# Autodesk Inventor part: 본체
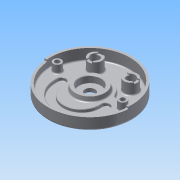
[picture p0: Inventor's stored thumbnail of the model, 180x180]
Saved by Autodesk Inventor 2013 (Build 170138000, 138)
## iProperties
Created: 2015-04
Part Number: 본체
Material: 알루미늄 6061
Document SubType Name: Modeling
Designer: Administrator
Density: 2.71 g/cm^3
Mass: 1042.47 g
Surface Area: 1020.69 cm^2
Volume: 384.675 cm^3
Author: Administrator
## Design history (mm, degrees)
sketch "스케치1"
  geometry: C1 r 95 at (0, 0); 1 further point
  constraints: 1 centre point, 1 coincident
  dimensions: "d0" = 95 radius of C1
extrude "돌출1" new body sketch "스케치1" distance "d1" = 27; taper "d2" = 0 deg
feature "쉘1" dims "d3" = 7, "d4" = 5
sketch "스케치2"
  geometry: L1 (-94.638, -8.28)-(-89.658, -7.844); L2 (89.658, -7.844)-(94.638, -8.28); L3 (0, 0)-(85.276, 0); L4 (-89.658, -7.844)-(0, 0); L5 (0, 0)-(89.658, -7.844); C1 r 90 at (0, 0) reference; A1 r 90 centre (0, 0) between (-89.658, -7.844) and (89.658, -7.844) reference; A2 r 95 centre (0, 0) between (-94.638, -8.28) and (94.638, -8.28) reference
  constraints: 10 end point, 4 point on circle, 2 collinear, 1 horizontal
  dimensions: "d5" = 5 deg angle of L2 L3; "d6" = 5 deg angle of L3 L1
extrude "돌출2" join sketch "스케치2" distance "d7" = 5; taper "d8" = 0 deg
sketch "스케치3"
  geometry: L1 (-40.249, 12)-(-89.196, 12); L2 (40.249, 12)-(89.196, 12); A1 r 90 centre (0, 0) between (-89.196, 12) and (89.196, 12) reference; A2 r 42 centre (0, 0) between (40.249, 12) and (-40.249, 12)
  constraints: 4 end point, 4 point on circle, 1 centre point, 1 coincident, 1 collinear, 1 horizontal
  dimensions: "d9" = 42 radius of A2; "d10" = 12 distance from line of A1.centre L1; "d12" = 12 distance from line of A1.centre L2
extrude "돌출3" join sketch "스케치3" distance "d13" = 7; taper "d14" = 0 deg
sketch "스케치4"
  geometry: C1 r 35 at (0, 0); A1 r 42 centre (0, 0) between (40.249, 12) and (-40.249, 12) reference
  constraints: 1 centre point, 1 coincident
  dimensions: "d15" = 70 diameter of C1
extrude "돌출4" join sketch "스케치4" distance "d16" = 10; taper "d17" = -10 deg
hole "구멍1" diameter "d20" = 23; stored, may be unused: countersink angle "d24" = 90 deg, drill point angle "d26" = 118 deg; dims "d18" = 10, "d19" = 10, "d21" = 6, "d22" = 50, "d23" = 15, "d25" = 8
fillet "모깎기1" dims "d27" = 0.3
sketch "스케치5"
  geometry: C1 r 35 at (0, 0) reference; A1 r 9 centre (-49.749, -14) between (-40.794, -14.9) and (-58.704, -13.1); A2 r 9 centre (49.749, -14) between (58.704, -13.1) and (40.794, -14.9); A3 r 59 centre (0, -19) between (-58.704, -13.1) and (58.704, -13.1); A4 r 41 centre (0, -19) between (-40.794, -14.9) and (40.794, -14.9)
  constraints: 8 point on circle, 4 centre point, 2 tangent, 1 coincident, 1 horizontal alignment, 1 vertical alignment
  dimensions: "d29" = 19 distance of A3.centre C1.centre; "d31" = 18 diameter of A1; "d32" = 18 diameter of A2; "d33" = 5 vertical distance of A3.centre A1.centre; "d34" = 41 radius of A4; "d35" = 59 radius of A3
extrude "돌출5" cut sketch "스케치5" distance "d36" = 7; taper "d37" = 0 deg
fillet "모깎기2" dims "d38" = 1
chamfer "모따기1" distance "d39" = 1; stored, may be unused: second distance "d40" = 2, angle "d41" = 45 deg
sketch "스케치6"
  geometry: C1 r 9 at (-74, 0); C2 r 9 at (74, 0); A1 r 90 centre (0, 0) between (-89.196, 12) and (89.196, 12) reference
  constraints: 2 centre point, 2 horizontal alignment
  dimensions: "d42" = 18 diameter of C1; "d43" = 18 diameter of C2; "d44" = 148 distance of C2.centre C1.centre; "d45" = 74 distance of A1.centre C2.centre
extrude "돌출6" join sketch "스케치6" stored distance "d46" = 7; taper "d47" = 0 deg
sketch "스케치7"
  geometry: C1 r 9 at (-74, 0) reference; C2 r 9 at (74, 0) reference; 2 further points
  constraints: 2 coincident
hole "구멍2" sketch "스케치7" at (-74, 0), (74, 0) diameter "d48" = 11; stored, may be unused: countersink angle "d52" = 90 deg, drill point angle "d54" = 118 deg; dims "d49" = 6, "d50" = 18, "d51" = 11, "d53" = 8
sketch "스케치8"
  geometry: C1 r 15 at (-40, 52); C2 r 15 at (40, 52); A1 r 42 centre (0, 0) between (40.249, 12) and (-40.249, 12) reference
  constraints: 2 centre point, 1 horizontal alignment
  dimensions: "d55" = 30 diameter of C1; "d56" = 30 diameter of C2; "d57" = 80 distance of C2.centre C1.centre; "d58" = 40 horizontal distance of A1.centre C1.centre; "d59" = 52 vertical distance of C1.centre A1.centre
extrude "돌출7" join sketch "스케치8" stored distance "d60" = 7; taper "d61" = 0 deg
sketch "스케치9"
  geometry: C1 r 15 at (0, 0) reference; C2 r 15 at (-80, 0) reference; C3 r 10 at (-80, 0); C4 r 10 at (0, 0); 1 further point
  constraints: 2 centre point, 2 coincident
  dimensions: "d62" = 20 diameter of C3; "d63" = 20 diameter of C4
extrude "돌출8" cut sketch "스케치9" stored distance "d64" = 7; taper "d65" = 0 deg
sketch "스케치10"
  geometry: L1 (6, -15)-(-6, -15); L2 (-6, -15)-(-6, 15); L3 (-6, 15)-(6, 15); L4 (6, 15)-(6, -15); L5 (6, -15)-(-6, 15); L6 (-6, -15)-(6, 15); L7 (95, -6)-(65, -6); L8 (65, -6)-(65, 6); L9 (65, 6)-(95, 6); L10 (95, 6)-(95, -6); L11 (95, -6)-(65, 6); L12 (65, -6)-(95, 6); C1 r 10 at (80, 0) reference; 5 further points
  constraints: 24 end point, 6 midpoint, 4 parallel, 2 horizontal, 2 perpendicular, 1 horizontal alignment, 1 vertical alignment, 2 other
  dimensions: "d66" = 12 distance of L2.end L3.end; "d68" = 12 distance of L7.end L8.end
extrude "돌출9" cut sketch "스케치10" distance "d69" = 3; taper "d70" = 0 deg
fillet "모깎기3" dims "d71" = 10
fillet "모깎기4" dims "d72" = 3
chamfer "모따기2" distance "d73" = 1; stored, may be unused: second distance "d74" = 2, angle "d75" = 45 deg
fillet "모깎기5" dims "d76" = 3
sketch "스케치13"
  geometry: L1 (0, 0)-(36.062, -36.062); L2 (0, 0)-(51, 0); L3 (36.062, -36.062)-(50.912, -50.912); L4 (0, 0)-(-36.062, -36.062); L5 (-50.912, -50.912)-(-36.062, -36.062); C1 r 12.5 at (0, 0) reference; A1 r 51 centre (0, 0) between (-36.062, -36.062) and (36.062, -36.062); A2 r 72 centre (0, 0) between (-50.912, -50.912) and (50.912, -50.912)
  constraints: 10 end point, 4 point on circle, 2 centre point, 2 coincident, 2 collinear, 1 equal length, 1 horizontal, 1 perpendicular
  dimensions: "d80" = 51 distance of L1.end L1.start; "d81" = 45 deg angle of L1 L2; "d82" = 72 radius of A2
extrude "돌출10" join sketch "스케치13" distance "d83" = 5; taper "d84" = 0 deg
fillet "모깎기6" dims "d85" = 5
fillet "모깎기7" dims "d86" = 3
fillet "모깎기8" dims "d87" = 5
sketch "스케치14"
  geometry: C1 r 68 at (0, 0); 1 further point
  constraints: 1 centre point, 1 coincident, 1 other
  dimensions: "d88" = 136 diameter of C1
feature "엠보싱2" sketch "스케치14" dims "d1" = 27, "d2" = 0, "d91" = 0.5, "d92" = 0
fillet "모깎기9" dims "d93" = 5
node "솔리드1"
node "투영된 루프1"
node "투영된 루프2"
other parameters: "d28" = 118, "d30" = 82, "d78" = 144
